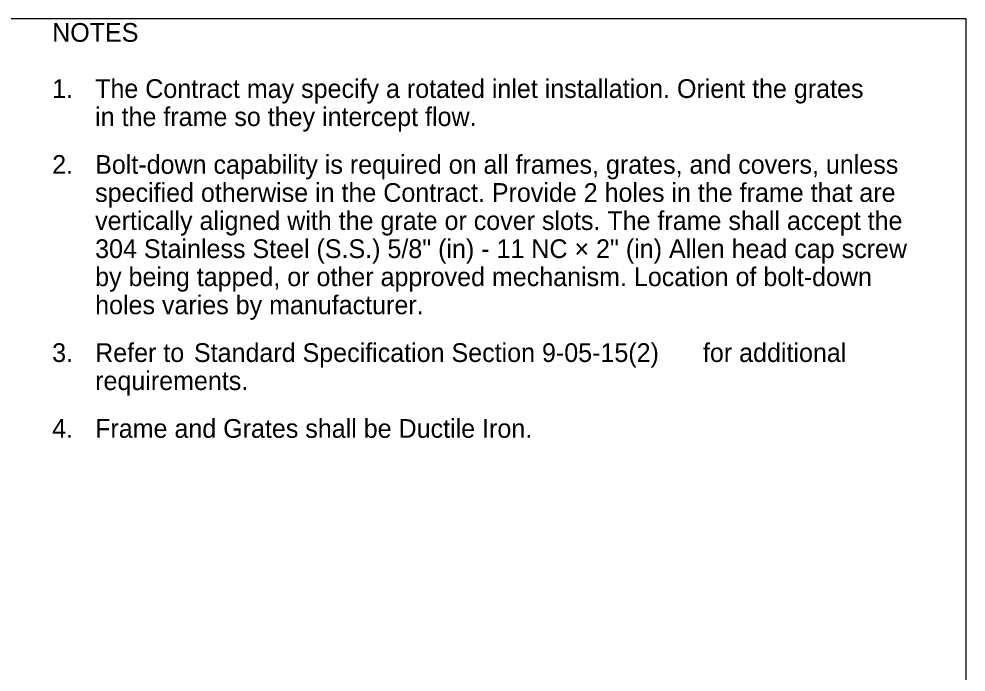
# Model space of a CAD drawing. Extents: x 99862 to 103151, y 100000 to 102076.
# Drawn here: x 102140 to 103151, y 101378 to 102076 of the extents above; entities that cross this region are included whole.
import ezdxf

# ---------------------------------------------------------------- set-up
doc = ezdxf.new("R2010")
doc.units = 0
for name, color, linetype in [('Level 1', 7, 'Continuous'), ('Level 20', 7, 'Continuous'), ('Level 60', 7, 'Continuous')]:
    doc.layers.add(name, color=color, linetype=linetype)

msp = doc.modelspace()

# ---------------------------------------------------------------- linework, layer by layer
at = {"layer": 'Level 1'}
msp.add_lwpolyline([(99862, 99999.5), (103151, 99999.5), (103151, 102075.5), (99862, 102075.5)], close=True, dxfattribs=at)
at = {"layer": 'Level 60'}
msp.add_line((103151, 102075.5), (103151, 102075.5), dxfattribs=at)

# ---------------------------------------------------------------- texts
at = {"layer": 'Level 20'}
for s, p in [('NOTES', (102175, 102051.1)), ('1.', (102175, 101991.1)), ('The Contract may specify a rotated inlet installation. Orient the grates', (102220.9, 101991.1)), ('in the frame so they intercept flow.', (102220.9, 101961.1)), ('2.', (102175, 101910.1)), ('Bolt-down capability is required on all frames, grates, and covers, unless', (102220.9, 101910.1)), ('specified otherwise in the Contract. Provide 2 holes in the frame that are', (102220.9, 101880.1)), ('vertically aligned with the grate or cover slots. The frame shall accept the', (102220.9, 101850.1)), ('304 Stainless Steel (S.S.) 5/8" (in) - 11 NC × 2" (in) Allen head cap screw', (102220.9, 101820.1)), ('by being tapped, or other approved mechanism. Location of bolt-down', (102220.9, 101790.1)), ('holes varies by manufacturer.', (102220.9, 101760.1)), ('3.', (102175, 101709.1)), ('Refer to', (102220.9, 101709.1)), (' Standard Specification Section 9-05-15(2) ', (102319, 101709.1)), ('for additional ', (102870, 101709.1)), ('requirements.', (102220.9, 101679.1)), ('4.', (102175, 101628.1)), ('Frame and Grates shall be Ductile Iron.', (102220.9, 101628.1))]:
    msp.add_text(s, height=20, dxfattribs=at).set_placement(p)

doc.saveas('drawing.dxf')
